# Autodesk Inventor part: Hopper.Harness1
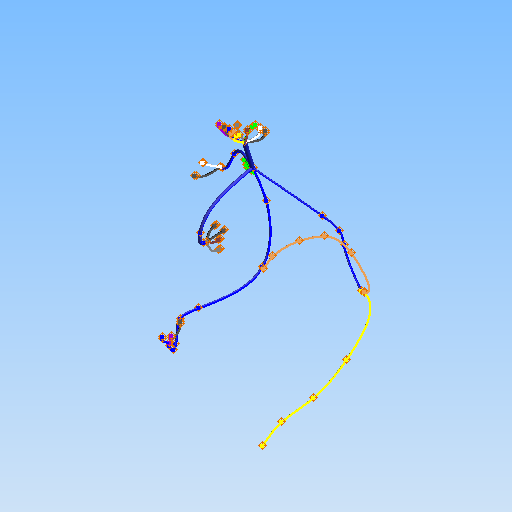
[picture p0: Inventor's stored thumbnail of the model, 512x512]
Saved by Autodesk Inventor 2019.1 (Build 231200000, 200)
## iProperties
GlobalPropertyList: <PropertyList/>
Key:2|1|1|0|4|0|0|0|18|0|0|0|Level:1: <CableProperty entityType="Connector" version="1.0"><ID editable="" value=""/><UserDefined/><Name editable="True" value=""/><Refdes editable="True" value="TERM1
Key:2|1|1|0|4|0|0|0|19|0|0|0|Level:1: <CableProperty entityType="Connector" version="1.0"><ID editable="" value=""/><UserDefined/><Name editable="True" value=""/><Refdes editable="True" value="TERM2
Key:2|1|1|0|4|0|0|0|20|0|0|0|Level:1: <CableProperty entityType="Connector" version="1.0"><ID editable="" value=""/><UserDefined/><Name editable="True" value=""/><Refdes editable="True" value="TERM3
Key:2|1|1|0|4|0|0|0|21|0|0|0|Level:1: <CableProperty entityType="Connector" version="1.0"><ID editable="" value=""/><UserDefined/><Name editable="True" value=""/><Refdes editable="True" value="TERM4
Key:2|1|1|0|4|0|0|0|22|0|0|0|Level:1: <CableProperty entityType="Connector" version="1.0"><ID editable="" value=""/><UserDefined/><Name editable="True" value=""/><Refdes editable="True" value="TERM5
Key:2|1|1|0|4|0|0|0|23|0|0|0|Level:1: <CableProperty entityType="Connector" version="1.0"><ID editable="" value=""/><UserDefined/><Name editable="True" value=""/><Refdes editable="True" value="TERM6
Key:2|1|1|0|4|0|0|0|24|0|0|0|Level:1: <CableProperty entityType="Connector" version="1.0"><ID editable="" value=""/><UserDefined/><Name editable="True" value=""/><Refdes editable="True" value="TERM7
Key:2|1|1|0|4|0|0|0|25|0|0|0|Level:1: <CableProperty entityType="Connector" version="1.0"><ID editable="" value=""/><UserDefined/><Name editable="True" value=""/><Refdes editable="True" value="TERM8
Key:2|1|1|0|4|0|0|0|26|0|0|0|Level:1: <CableProperty entityType="Connector" version="1.0"><ID editable="" value=""/><UserDefined/><Name editable="True" value=""/><Refdes editable="True" value="TERM9
Key:2|1|1|0|4|0|0|0|27|0|0|0|Level:1: <CableProperty entityType="Connector" version="1.0"><ID editable="" value=""/><UserDefined/><Name editable="True" value=""/><Refdes editable="True" value="TERM1
Key:2|1|1|0|4|0|0|0|28|0|0|0|Level:1: <CableProperty entityType="Connector" version="1.0"><ID editable="" value=""/><UserDefined/><Name editable="True" value=""/><Refdes editable="True" value="TERM1
Key:2|1|1|0|4|0|0|0|29|0|0|0|Level:1: <CableProperty entityType="Connector" version="1.0"><ID editable="" value=""/><UserDefined/><Name editable="True" value=""/><Refdes editable="True" value="TERM1
Key:2|1|1|0|4|0|0|0|30|0|0|0|Level:1: <CableProperty entityType="Connector" version="1.0"><ID editable="" value=""/><UserDefined/><Name editable="True" value=""/><Refdes editable="True" value="J1" o
Key:2|1|2|0|36|0|0|0|2|1|1|0|4|0|0|0|30|0|0|0|16|2|0|0|16|0|: <CableProperty entityType="ConnectorPin" version="1.0"><ID editable="" value=""/><UserDefined/><PinName editable="True" value="1"/><AttachedParts><AttachedPart 
Key:2|1|2|0|36|0|0|0|2|1|1|0|4|0|0|0|30|0|0|0|16|2|0|0|16|0|: <CableProperty entityType="ConnectorPin" version="1.0"><ID editable="" value=""/><UserDefined/><PinName editable="True" value="2"/><AttachedParts><AttachedPart 
Key:2|1|2|0|36|0|0|0|2|1|1|0|4|0|0|0|30|0|0|0|16|2|0|0|16|0|: <CableProperty entityType="ConnectorPin" version="1.0"><ID editable="" value=""/><UserDefined/><PinName editable="True" value="3"/><AttachedParts><AttachedPart 
Key:2|1|2|0|36|0|0|0|2|1|1|0|4|0|0|0|30|0|0|0|16|2|0|0|16|0|: <CableProperty entityType="ConnectorPin" version="1.0"><ID editable="" value=""/><UserDefined/><PinName editable="True" value="9"/><AttachedParts><AttachedPart 
Key:2|1|2|0|36|0|0|0|2|1|1|0|4|0|0|0|30|0|0|0|16|2|0|0|16|0|: <CableProperty entityType="ConnectorPin" version="1.0"><ID editable="" value=""/><UserDefined/><PinName editable="True" value="11"/><AttachedParts><AttachedPart
Key:2|1|2|0|36|0|0|0|2|1|1|0|4|0|0|0|30|0|0|0|16|2|0|0|16|0|: <CableProperty entityType="ConnectorPin" version="1.0"><ID editable="" value=""/><UserDefined/><PinName editable="True" value="19"/><AttachedParts><AttachedPart
Key:2|1|2|0|36|0|0|0|2|1|1|0|4|0|0|0|30|0|0|0|16|2|0|0|16|0|: <CableProperty entityType="ConnectorPin" version="1.0"><ID editable="" value=""/><UserDefined/><PinName editable="True" value="18"/><AttachedParts><AttachedPart
Key:2|1|2|0|36|0|0|0|2|1|1|0|4|0|0|0|30|0|0|0|16|2|0|0|16|0|: <CableProperty entityType="ConnectorPin" version="1.0"><ID editable="" value=""/><UserDefined/><PinName editable="True" value="17"/><AttachedParts><AttachedPart
Key:2|1|2|0|36|0|0|0|2|1|1|0|4|0|0|0|30|0|0|0|16|2|0|0|16|0|: <CableProperty entityType="ConnectorPin" version="1.0"><ID editable="" value=""/><UserDefined/><PinName editable="True" value="16"/><AttachedParts><AttachedPart
Key:2|1|2|0|36|0|0|0|2|1|1|0|4|0|0|0|30|0|0|0|16|2|0|0|16|0|: <CableProperty entityType="ConnectorPin" version="1.0"><ID editable="" value=""/><UserDefined/><PinName editable="True" value="15"/><AttachedParts><AttachedPart
Created: 2005-11
Part Number: Hopper.Harness1
Document SubType Name: Modeling
Designer: floress
Material: Default
Density: 1 g/cm^3
Appearance: Default
Author: floress
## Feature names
1. Sweep22
2. Sweep52
3. Sweep56
4. Sweep94
5. Sweep139
6. Sweep140
7. Sweep153
8. Sweep154
9. Sweep157
10. Sweep158
11. Sweep168
12. Sweep183
13. Sweep184
14. Sweep185
15. Sweep186
16. Sweep187
17. Sweep188
18. Sweep189
19. Sweep190
20. Sweep191
21. Sweep192
22. Sweep193
23. Sweep194
24. Sweep195
25. Sweep196
26. Sweep197
27. Sweep198
## Parameters: d21 = 0, d51 = 0, d55 = 0, d93 = 0, d138 = 0, d139 = 0, d152 = 0, d153 = 0, d156 = 0, d157 = 0, d167 = 0, d182 = 0, d183 = 0, d184 = 0, d185 = 0, d186 = 0, d187 = 0, d188 = 0, d189 = 0, d190 = 0, d191 = 0, d192 = 0, d193 = 0, d194 = 0, d195 = 0, d196 = 0, d197 = 0, d198 = 0, d199 = 0, d200 = 0, d201 = 0, d202 = 0, d203 = 0, d204 = 0, d205 = 0, d206 = 0, d207 = 0, d208 = 0, d209 = 0, d210 = 0, d211 = 0, d212 = 0, d213 = 0, d214 = 0, d215 = 0, d216 = 0, d217 = 0, d218 = 0, d219 = 0, d220 = 0, d221 = 0, d222 = 0, d223 = 0, d224 = 0
